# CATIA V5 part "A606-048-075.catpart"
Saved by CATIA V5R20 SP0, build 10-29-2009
Part number: A606-048-075
Source: Unknown
Property "ARTICLENO": "A606-048-075"
Property "BOMINFO": "A606-048-075"
Property "CODE": "A606-048-075"
Property "HOLES": "2"
Property "L": "75.000"
Property "L1": "15.000"
Property "L2": "45.000"
Property "LINA": "A606-048-075"
Property "NB": "A606-048-075"
Property "NBSYN": "$CODE."
Property "NN": "A606"
Property "NT": "Wear Plates, self-lubricating"
Property "SCREW": "2xM6"
Property "SUPPLIER": "CF"
Property "W": "48.000"
Bounding box of the stored display mesh (mm): x -24 to 24, y -5 to 5, z -37.5 to 37.5
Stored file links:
  C:\Users\Utente\Desktop\3D files A606\A606-048-075.catpart
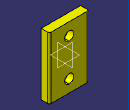
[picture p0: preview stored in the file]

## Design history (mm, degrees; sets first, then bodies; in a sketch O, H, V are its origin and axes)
Body1 "Geometry.1" (main body)
  Solid1 "A606-048-075.catpart": solid without history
